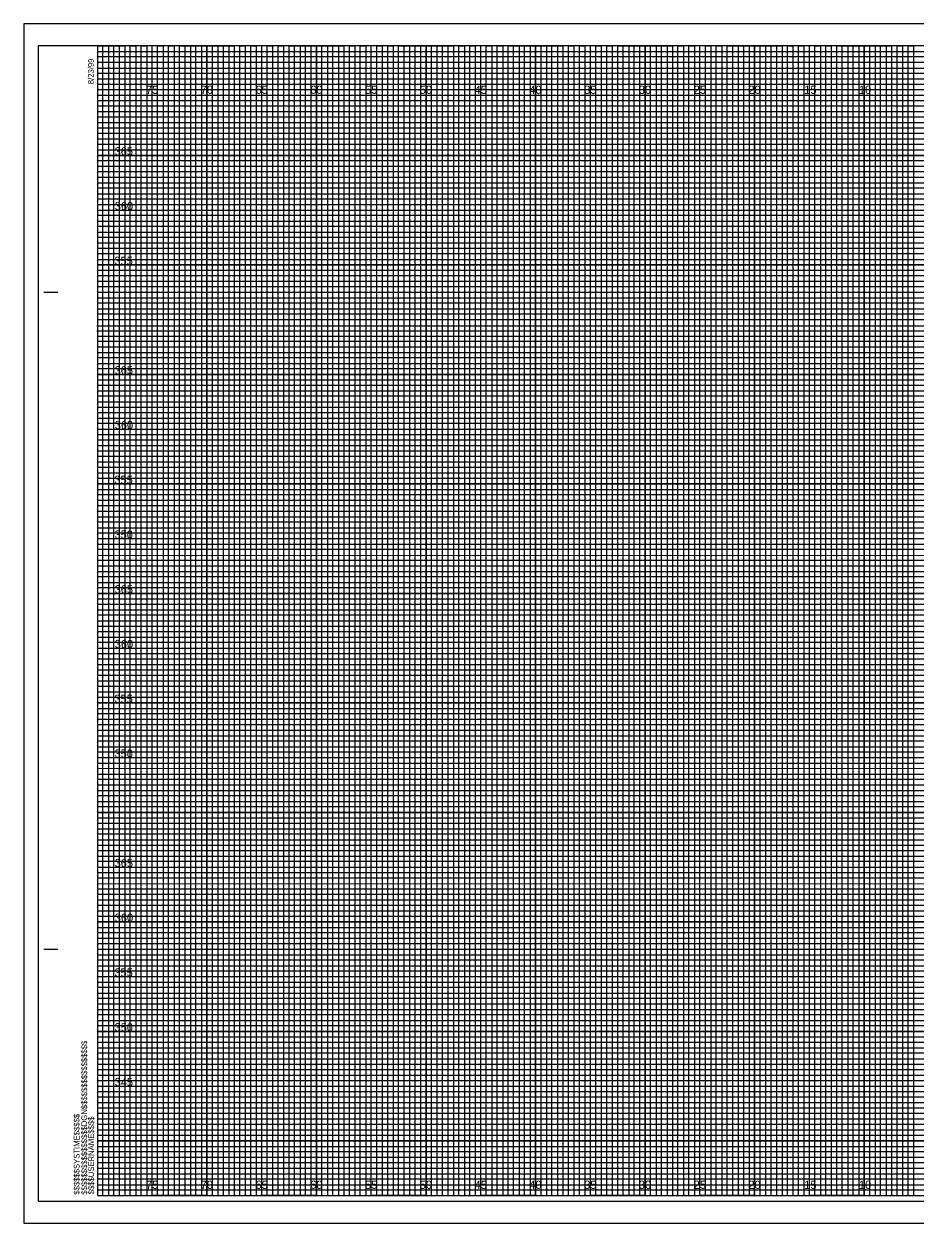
# Model space of a CAD drawing. Extents: x -7 to 266, y -5 to 437.
# Drawn here: x -6.7 to 74.6, y 217.5 to 327 of the extents above; entities that cross this region are included whole.
import ezdxf

# ---------------------------------------------------------------- set-up
doc = ezdxf.new("R2010")
doc.units = 0
for name, color, linetype in [('Exist XS Center Line Elevation Label', 7, 'Continuous'), ('Exist XS Ground Line', 7, 'Continuous'), ('Prop XS Finish Grade', 7, 'Continuous'), ('Prop XS Finish Grade Concrete', 7, 'Continuous'), ('Prop XS Finish Grade Earthwork', 7, 'Continuous'), ('Prop XS Hydro Elevations', 7, 'Continuous'), ('Prop XS Pvmt Edge Slope', 7, 'Continuous'), ('Prop XS SE Text', 7, 'Continuous'), ('Prop XS SS Elevation Text', 7, 'Continuous'), ('Prop XS Subgrade Earthwork', 7, 'Continuous'), ('Typical Guardrail CELL', 7, 'Continuous')]:
    doc.layers.add(name, color=color, linetype=linetype)

msp = doc.modelspace()

# ---------------------------------------------------------------- linework, layer by layer
at = {"layer": 'Exist XS Center Line Elevation Label'}
for points in [[(0, 325), (2.5, 325), (2.5, 220), (7.5, 220), (7.5, 325), (12.5, 325), (12.5, 220), (17.5, 220), (17.5, 325), (22.5, 325), (22.5, 220), (27.5, 220), (27.5, 325), (32.5, 325), (32.5, 220), (37.5, 220), (37.5, 325), (42.5, 325), (42.5, 220), (47.5, 220), (47.5, 325), (52.5, 325), (52.5, 220), (57.5, 220), (57.5, 325), (62.5, 325), (62.5, 220), (67.5, 220), (67.5, 325), (72.5, 325), (72.5, 220), (77.5, 220)], [(0, 322.5), (137.5, 322.5)], [(0, 312.5), (160, 312.5), (160, 317.5), (0, 317.5)], [(0, 302.5), (160, 302.5), (160, 307.5), (0, 307.5)], [(0, 292.5), (160, 292.5), (160, 297.5), (0, 297.5)], [(0, 282.5), (160, 282.5), (160, 287.5), (0, 287.5)], [(0, 272.5), (160, 272.5), (160, 277.5), (0, 277.5)], [(0, 262.5), (160, 262.5), (160, 267.5), (0, 267.5)], [(0, 252.5), (160, 252.5), (160, 257.5), (0, 257.5)], [(0, 242.5), (160, 242.5), (160, 247.5), (0, 247.5)], [(0, 232.5), (160, 232.5), (160, 237.5), (0, 237.5)], [(0, 222.5), (160, 222.5), (160, 227.5), (0, 227.5)]]:
    msp.add_lwpolyline(points, dxfattribs=at)
at = {"layer": 'Exist XS Ground Line'}
for p, q in [((5, 325), (0, 325)), ((5, 220), (5, 325)), ((15, 325), (10, 325)), ((10, 325), (10, 220)), ((15, 220), (15, 325)), ((25, 325), (20, 325)), ((20, 325), (20, 220)), ((25, 220), (25, 325)), ((35, 325), (30, 325)), ((30, 325), (30, 220)), ((35, 220), (35, 325)), ((45, 325), (40, 325)), ((40, 325), (40, 220)), ((45, 220), (45, 325)), ((55, 325), (50, 325)), ((50, 325), (50, 220)), ((55, 220), (55, 325)), ((65, 325), (60, 325)), ((60, 325), (60, 220)), ((65, 220), (65, 325)), ((75, 325), (70, 325)), ((70, 325), (70, 220)), ((10, 220), (5, 220)), ((20, 220), (15, 220)), ((30, 220), (25, 220)), ((40, 220), (35, 220)), ((50, 220), (45, 220)), ((60, 220), (55, 220)), ((70, 220), (65, 220))]:
    msp.add_line(p, q, dxfattribs=at)
for points in [[(0, 320), (160, 320), (160, 315), (0, 315)], [(0, 310), (160, 310), (160, 305), (0, 305)], [(0, 300), (160, 300), (160, 295), (0, 295)], [(0, 290), (160, 290), (160, 285), (0, 285)], [(0, 280), (160, 280), (160, 275), (0, 275)], [(0, 270), (160, 270), (160, 265), (0, 265)], [(0, 260), (160, 260), (160, 255), (0, 255)], [(0, 250), (160, 250), (160, 245), (0, 245)], [(0, 240), (160, 240), (160, 235), (0, 235)], [(0, 230), (160, 230), (160, 225), (0, 225)]]:
    msp.add_lwpolyline(points, dxfattribs=at)
at = {"layer": 'Prop XS Finish Grade'}
for p, q in [((5, 220), (5, 325)), ((10, 220), (10, 325)), ((15, 220), (15, 325)), ((20, 220), (20, 325)), ((25, 220), (25, 325)), ((30, 220), (30, 325)), ((35, 220), (35, 325)), ((40, 220), (40, 325)), ((45, 220), (45, 325)), ((50, 220), (50, 325)), ((55, 220), (55, 325)), ((60, 220), (60, 325)), ((65, 220), (65, 325)), ((70, 220), (70, 325)), ((0, 320), (160, 320)), ((0, 315), (160, 315)), ((0, 310), (160, 310)), ((0, 305), (160, 305)), ((0, 300), (160, 300)), ((0, 295), (160, 295)), ((0, 290), (160, 290)), ((0, 285), (160, 285)), ((0, 280), (160, 280)), ((0, 275), (160, 275)), ((0, 270), (160, 270)), ((0, 265), (160, 265)), ((0, 260), (160, 260)), ((0, 255), (160, 255)), ((0, 250), (160, 250)), ((0, 245), (160, 245)), ((0, 240), (160, 240)), ((0, 235), (160, 235)), ((0, 230), (160, 230)), ((0, 225), (160, 225))]:
    msp.add_line(p, q, dxfattribs=at)
at = {"layer": 'Prop XS Finish Grade Earthwork'}
msp.add_lwpolyline([(-6.7, 217.5), (161.65, 217.5), (161.65, 327), (-6.7, 327)], close=True, dxfattribs=at)
at = {"layer": 'Prop XS Hydro Elevations'}
for p, q in [((-4.9, 302.5), (-3.65, 302.5)), ((-4.85, 302.5), (-3.6, 302.5)), ((-4.9, 242.5), (-3.65, 242.5)), ((-4.85, 242.5), (-3.6, 242.5)), ((0, 220), (0, 220)), ((0, 220), (0, 220)), ((0, 220), (0, 220)), ((0, 220), (0, 220)), ((0, 220), (0, 220)), ((0, 220), (0, 220)), ((0, 220), (0, 220))]:
    msp.add_line(p, q, dxfattribs=at)
msp.add_lwpolyline([(160, 325), (0, 325), (0, 220), (160, 220)], close=True, dxfattribs=at)
at = {"layer": 'Prop XS Pvmt Edge Slope'}
msp.add_lwpolyline([(-5.4, 219.5), (161.2, 219.5), (161.2, 325), (-5.4, 325)], close=True, dxfattribs=at)
at = {"layer": 'Prop XS SE Text'}
for p, q in [((0, 324.5), (130, 324.5)), ((130, 323.99), (0, 323.99)), ((0, 323.99), (0, 323.5)), ((0, 323.5), (130, 323.5)), ((130, 322.94), (0, 322.94)), ((0, 322.94), (0, 322)), ((0, 322), (160, 322))]:
    msp.add_line(p, q, dxfattribs=at)
for points in [[(0, 321.5), (135, 321.5), (160, 321.5), (160, 321), (0, 321)], [(0, 320.5), (160, 320.5), (160, 319.5), (0, 319.5)], [(0, 319), (160, 319), (160, 318.5), (0, 318.49)], [(0, 318), (160, 318), (160, 317), (0, 317)], [(0, 316.5), (160, 316.5), (160, 316), (0, 316)], [(0, 315.5), (160, 315.5), (160, 314.5), (0, 314.5)], [(0, 314), (160, 314), (160, 313.5), (0, 313.5)], [(0, 313), (160, 313), (160, 312), (0, 312)], [(0, 311.5), (160, 311.5), (160, 311), (0, 311)], [(0, 310.5), (160, 310.5), (160, 309.5), (0, 309.5)], [(0, 309), (160, 309), (160, 308.5), (0, 308.5)], [(0, 308), (160, 308), (160, 306.98), (160, 306.5), (160, 306), (0, 306)], [(0, 307), (160, 307), (160, 306.5), (0, 306.5)], [(0, 305.5), (160, 305.5), (160, 304.5), (0, 304.51)], [(0, 304.51), (160, 304.5), (160, 304), (0, 304)], [(0, 303.5), (160, 303.5), (160, 303), (0, 303)], [(0, 302), (160, 302), (160, 301.5), (0, 301.5)], [(0, 301), (160, 301), (160, 300.5), (0, 300.5)], [(-0.04, 299.44), (160, 299.44), (160, 298.94), (-0.04, 298.94)], [(0, 298.5), (160, 298.5), (160, 298), (0, 298)], [(0, 297), (160, 297), (160, 296.5), (0, 296.5)], [(0, 296), (160, 296), (160, 295.5), (0, 295.5)], [(0, 294.5), (160, 294.5), (160, 294), (0, 294)], [(0, 293.5), (160, 293.5), (160, 293), (0, 293)], [(0, 292), (160, 292), (160, 291.5), (0, 291.5)], [(0, 291), (160, 291), (160, 290.5), (0, 290.5)], [(0, 289.5), (160, 289.5), (160, 288.99), (0, 289)], [(0, 288.5), (160, 288.5), (160, 288), (0, 288)], [(0, 287), (160, 287), (160, 286.5), (0, 286.5)], [(0, 286), (160, 286), (160, 285.5), (0, 285.5)], [(0, 284.5), (160, 284.5), (160, 284), (0, 284)], [(0, 283.5), (160, 283.5), (160, 283), (0, 283)], [(0, 282), (160, 282), (160, 281.5), (0, 281.5)], [(0, 281), (160, 281), (160, 280.5), (0, 280.5)], [(0, 279.5), (160, 279.5), (160, 279), (0, 279)], [(0, 278.5), (160.03, 278.45), (160, 278), (0, 278)], [(0, 277), (160, 277), (160, 276.5), (0, 276.5)], [(0, 276), (160, 276), (160, 275.5), (0, 275.5)], [(0, 274.5), (160, 274.5), (160, 274), (0, 274)], [(0, 273.5), (160, 273.5), (160, 273), (0, 273)], [(0, 272), (160, 272), (160, 271.5), (0, 271.5)], [(0, 271), (160, 271), (160, 270.5), (0, 270.5)], [(0, 269.5), (160, 269.5), (160, 269), (0, 269)], [(0, 268.5), (160, 268.5), (160, 268), (0, 268)], [(0, 267), (160, 267), (160, 266.5), (0, 266.5)], [(0, 266), (160, 266), (160, 265.5), (0, 265.5)], [(0, 264.5), (160, 264.5), (160, 264), (0, 264)], [(0, 263.5), (160, 263.5), (160, 263), (0, 263)], [(0, 262), (160, 262), (160, 261.5), (0, 261.5)], [(0, 261), (160, 261), (160, 260.5), (0, 260.5)], [(0, 259.5), (160, 259.5), (160, 258.99), (0, 259)], [(0, 258.5), (160, 258.5), (160, 258), (0, 258)], [(0, 257), (160, 257), (160, 256.5), (0, 256.5)], [(0, 256), (160, 256), (160, 255.5), (0, 255.5)], [(0, 254.5), (160, 254.5), (160, 254), (0, 254)], [(0, 253.5), (160, 253.5), (160, 253), (0, 253)], [(0, 252), (160, 252), (160, 251.5), (0, 251.5)], [(0, 251), (160, 251), (160, 250.5), (0, 250.5)], [(0, 249.5), (160, 249.5), (160, 249), (0, 249)], [(0, 248.5), (160.03, 248.46), (160, 248), (0, 248)], [(0, 247), (160, 247), (160, 246.5), (0, 246.5)], [(0, 246), (160, 246), (160, 245.5), (0, 245.5)], [(0, 244.5), (160, 244.5), (160, 244), (0, 244)], [(0, 243.5), (160, 243.5), (160, 243), (0, 243)], [(0, 242), (160, 242), (160, 241.5), (0, 241.5)], [(0, 241), (160, 241), (160, 240.5), (0, 240.5)], [(0, 239.5), (160, 239.5), (160, 239), (0, 239)], [(0, 238.5), (160, 238.5), (160, 238), (0, 238)], [(0, 237), (160, 237), (160, 236.5), (0, 236.5)], [(0, 236), (160, 236), (160, 235.5), (0, 235.5)], [(0, 234.5), (160, 234.5), (160, 234), (0, 234)], [(0, 233.5), (160, 233.5), (160, 233), (0, 233)], [(0, 232), (160, 232), (160, 231.5), (0, 231.5)], [(0, 231), (160, 231), (160, 230.5), (0, 230.5)], [(0, 229.5), (160, 229.5), (160, 229), (0, 229)], [(0, 228.5), (160, 228.5), (160, 228), (0, 228)], [(0, 227), (160, 227), (160, 226.5), (0, 226.5)], [(0, 226), (160, 226), (160, 225.5), (0, 225.5)], [(0, 224.5), (160, 224.5), (160, 224), (0, 224)], [(0, 223.5), (160, 223.5), (160, 223), (0, 223)], [(0, 222), (160, 222), (160, 221.5), (0, 221.5)], [(0, 221), (160, 221), (160, 220.5), (0, 220.5)]]:
    msp.add_lwpolyline(points, dxfattribs=at)
at = {"layer": 'Prop XS SS Elevation Text'}
for points in [[(0, 220), (0.5, 220), (0.5, 325), (1, 325), (1, 220)], [(1, 220), (1.5, 220), (1.5, 325), (2, 325), (2, 220)], [(2.5, 220), (3, 220), (3, 325), (3.5, 325), (3.5, 220)], [(3.5, 220), (4, 220), (4, 325), (4.5, 325), (4.5, 220)], [(5, 220), (5.5, 220), (5.5, 325), (6, 325), (6, 220)], [(6, 220), (6.5, 220), (6.5, 325), (7, 325), (7, 220)], [(7.5, 220), (8, 220), (8, 325), (8.5, 325), (8.5, 220)], [(8.5, 220), (9, 220), (9, 325), (9.5, 325), (9.5, 220)], [(10, 220), (10.5, 220), (10.5, 325), (11, 325), (11, 220)], [(11, 220), (11.5, 220), (11.5, 325), (12, 325), (12, 220)], [(12.5, 220), (13, 220), (13, 325), (13.5, 325), (13.5, 220)], [(13.5, 220), (14, 220), (14, 325), (14.5, 325), (14.5, 220)], [(15, 220), (15.5, 220), (15.5, 325), (16, 325), (16, 220)], [(16, 220), (16.5, 220), (16.5, 325), (17, 325), (17, 220)], [(17.5, 220), (18, 220), (18, 325), (18.5, 325), (18.5, 220)], [(18.5, 220), (19, 220), (19, 325), (19.5, 325), (19.5, 220)], [(20, 220), (20.5, 220), (20.5, 325), (21, 325), (21, 220)], [(21, 220), (21.5, 220), (21.5, 325), (22, 325), (22, 220)], [(22.5, 220), (23, 220), (23, 325), (23.5, 325), (23.5, 220)], [(23.5, 220), (24, 220), (24, 325), (24.5, 325), (24.5, 220)], [(25, 220), (25.5, 220), (25.5, 325), (26, 325), (26, 220)], [(26, 220), (26.5, 220), (26.5, 325), (27, 325), (27, 220)], [(27.5, 220), (28, 220), (28, 325), (28.5, 325), (28.5, 220)], [(28.5, 220), (29, 220), (29, 325), (29.5, 325), (29.5, 220)], [(30, 220), (30.5, 220), (30.5, 325), (31, 325), (31, 220)], [(31, 220), (31.5, 220), (31.5, 325), (32, 325), (32, 220)], [(32.5, 220), (33, 220), (33, 325), (33.5, 325), (33.5, 220)], [(33.5, 220), (34, 220), (34, 325), (34.5, 325), (34.5, 220)], [(35, 220), (35.5, 220), (35.5, 325), (36, 325), (36, 220)], [(36, 220), (36.5, 220), (36.5, 325), (37, 325), (37, 220)], [(37.5, 220), (38, 220), (38, 325), (38.5, 325), (38.5, 220)], [(38.5, 220), (39, 220), (39, 325), (39.5, 325), (39.5, 220)], [(40, 220), (40.5, 220), (40.5, 325), (41, 325), (41, 220)], [(41, 220), (41.5, 220), (41.5, 325), (42, 325), (42, 220)], [(42.5, 220), (43, 220), (43, 325), (43.5, 325), (43.5, 220)], [(43.5, 220), (44, 220), (44, 325), (44.5, 325), (44.5, 220)], [(45, 220), (45.5, 220), (45.5, 325), (46, 325), (46, 220)], [(46, 220), (46.5, 220), (46.5, 325), (47, 325), (47, 220)], [(47.5, 220), (48, 220), (48, 325), (48.5, 325), (48.5, 220)], [(48.5, 220), (49, 220), (49, 325), (49.5, 325), (49.5, 220)], [(50, 220), (50.5, 220), (50.5, 325), (51, 325), (51, 220)], [(51, 220), (51.5, 220), (51.5, 325), (52, 325), (52, 220)], [(52.5, 220), (53, 220), (53, 325), (53.5, 325), (53.5, 220)], [(53.5, 220), (54, 220), (54, 325), (54.5, 325), (54.5, 220)], [(55, 220), (55.5, 220), (55.5, 325), (56, 325), (56, 220)], [(56, 220), (56.5, 220), (56.5, 325), (57, 325), (57, 220)], [(57.5, 220), (58, 220), (58, 325), (58.5, 325), (58.5, 220)], [(58.5, 220), (59, 220), (59, 325), (59.5, 325), (59.5, 220)], [(60, 220), (60.5, 220), (60.5, 325), (61, 325), (61, 220)], [(61, 220), (61.5, 220), (61.5, 325), (62, 325), (62, 220)], [(62.5, 220), (63, 220), (63, 325), (63.5, 325), (63.5, 220)], [(63.5, 220), (64, 220), (64, 325), (64.5, 325), (64.5, 220)], [(65, 220), (65.5, 220), (65.5, 325), (66, 325), (66, 220)], [(66, 220), (66.5, 220), (66.5, 325), (67, 325), (67, 220)], [(67.5, 220), (68, 220), (68, 325), (68.5, 325), (68.5, 220)], [(68.5, 220), (69, 220), (69, 325), (69.5, 325), (69.5, 220)], [(70, 220), (70.5, 220), (70.5, 325), (71, 325), (71, 220)], [(71, 220), (71.5, 220), (71.5, 325), (72, 325), (72, 220)], [(72.5, 220), (73, 220), (73, 325), (73.5, 325), (73.5, 220)], [(73.5, 220), (74, 220), (74, 325), (74.5, 325), (74.5, 220)]]:
    msp.add_lwpolyline(points, dxfattribs=at)
at = {"layer": 'Prop XS Subgrade Earthwork'}
for p, q in [((161.65, 327), (-6.7, 327)), ((-6.7, 327), (-6.7, 217.5)), ((-6.7, 217.5), (161.65, 217.5))]:
    msp.add_line(p, q, dxfattribs=at)

# ---------------------------------------------------------------- texts
at = {"layer": 'Prop XS Finish Grade Concrete'}
for s, p in [('365', (1.58, 315)), ('360', (1.59, 310)), ('355', (1.56, 305)), ('365', (1.58, 295)), ('360', (1.59, 290)), ('355', (1.56, 285)), ('350', (1.57, 280)), ('365', (1.58, 275)), ('360', (1.59, 270)), ('355', (1.56, 265)), ('350', (1.57, 260)), ('365', (1.58, 250)), ('360', (1.59, 245)), ('355', (1.56, 240)), ('350', (1.57, 235)), ('345', (1.58, 230))]:
    msp.add_text(s, height=0.75, dxfattribs=at).set_placement(p)
at = {"layer": 'Prop XS Hydro Elevations'}
for s, p in [('8/23/99', (-0.33, 321.5)), ('$$$$$$$$$$$$$$$$DGN$$$$$$$$$$$$$$$$', (-0.94, 220.09)), ('$$$$$$SYSTIME$$$$$', (-1.63, 220.09)), ('$$$$USERNAME$$$$', (-0.31, 220.12))]:
    msp.add_text(s, height=0.525, rotation=90, dxfattribs=at).set_placement(p)
at = {"layer": 'Typical Guardrail CELL'}
for s, p in [('75', (4.44, 320.62)), ('70', (9.43, 320.62)), ('65', (14.44, 320.62)), ('60', (19.43, 320.62)), ('55', (24.44, 320.62)), ('50', (29.43, 320.62)), ('45', (34.44, 320.62)), ('40', (39.43, 320.62)), ('35', (44.44, 320.62)), ('30', (49.43, 320.62)), ('25', (54.44, 320.62)), ('20', (59.43, 320.62)), ('15', (64.53, 320.62)), ('10', (69.52, 320.62)), ('75', (4.44, 220.62)), ('70', (9.43, 220.62)), ('65', (14.44, 220.62)), ('60', (19.43, 220.62)), ('55', (24.44, 220.62)), ('50', (29.43, 220.62)), ('45', (34.44, 220.62)), ('40', (39.43, 220.62)), ('35', (44.44, 220.62)), ('30', (49.43, 220.62)), ('25', (54.44, 220.62)), ('20', (59.43, 220.62)), ('15', (64.53, 220.62)), ('10', (69.52, 220.62))]:
    msp.add_text(s, height=0.75, dxfattribs=at).set_placement(p)

doc.saveas('drawing.dxf')
